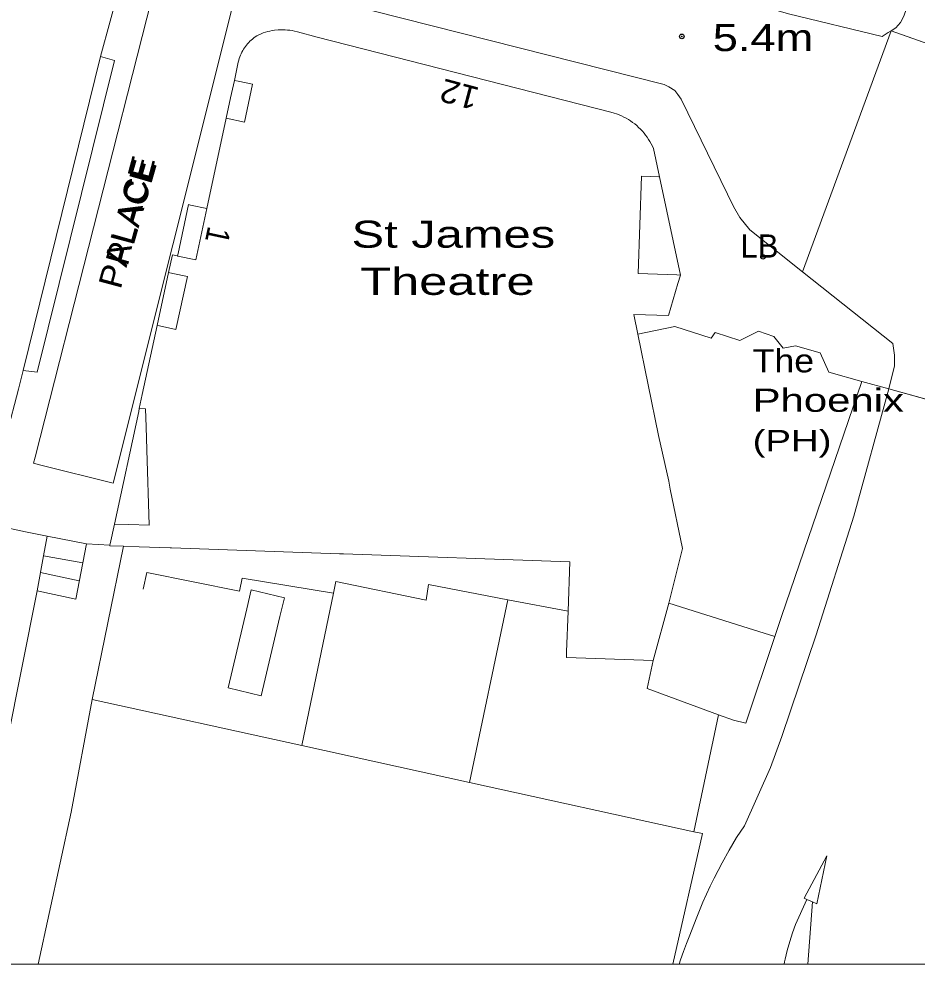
# Model space of a CAD drawing. Extents: x 528790 to 529292, y 179350 to 179856.
# Drawn here: x 529015 to 529073.1, y 179356 to 179417.1 of the extents above; entities that cross this region are included whole.
import ezdxf

# ---------------------------------------------------------------- set-up
doc = ezdxf.new("R2010")
doc.units = 0
doc.header["$LTSCALE"] = 0.6
doc.header["$PDMODE"] = 32
doc.header["$PDSIZE"] = 0.3
for name, color, linetype, lineweight in [('1', 7, 'Continuous', 13), ('2', 7, 'Continuous', 13), ('7', 7, 'Continuous', 13)]:
    doc.layers.add(name, color=color, linetype=linetype, lineweight=lineweight)
doc.layers.add('3', color=7, linetype='Continuous')
doc.layers.add('5', color=7, linetype='Continuous')

msp = doc.modelspace()

# ---------------------------------------------------------------- linework, layer by layer
at = {"layer": '1'}
for points in [[(529098.25, 179465.2), (529099.6, 179467.2), (529101.25, 179469.3), (529102.95, 179471.55), (529104.35, 179473.5), (529107.6, 179479.8), (529101.31, 179483.07), (529100.25, 179481.25), (529098.95, 179478.8), (529097.6, 179476.3), (529096.35, 179473.9), (529094.8, 179471.55), (529094, 179470.3), (529093, 179469.05), (529089.8, 179465.7), (529088.7, 179464.65), (529072.2, 179417.3), (529072, 179416.9), (529071.7, 179416.55), (529071.39, 179416.36), (529080.46, 179413.16)], [(529065.66, 179400.79), (529071.39, 179416.36), (529071.2, 179416.25), (529070.8, 179416), (529064.75, 179417.45), (529051.75, 179421.2), (529039.55, 179424.7), (529033.24, 179426.5), (529031.249, 179419.354), (529032.25, 179419.1), (529056.7, 179412.9), (529057, 179412.75), (529057.4, 179412.5), (529057.6, 179412.25), (529057.8, 179411.95), (529060.8, 179405.8), (529061.2, 179405), (529061.6, 179404.3), (529062.25, 179403.5)], [(529015.25, 179394.4), (529016.15, 179394.3), (529021.15, 179414.45), (529020.25, 179414.7)], [(529028.383, 179410.711), (529029.556, 179410.459), (529030.082, 179412.903), (529029.154, 179413.103), (529028.91, 179413.155), (529028.667, 179412.029)], [(529057.76, 179400.572), (529056.403, 179406.926), (529056.354, 179406.918), (529055.237, 179406.972), (529055.024, 179400.665), (529057.535, 179400.588)], [(529027.125, 179404.874), (529026.079, 179405.1), (529025.952, 179405.127), (529025.273, 179401.973), (529025.237, 179401.804), (529025.249, 179401.801), (529026.409, 179401.55)], [(529023.922, 179397.321), (529024.064, 179397.291), (529025.135, 179397.06), (529025.872, 179400.481), (529024.939, 179400.682), (529024.66, 179400.742)], [(529069.5, 179393.7), (529067.35, 179394.3), (529066.8, 179395.55), (529065.2, 179396), (529064.4, 179395.85), (529063.8, 179396.6), (529062.8, 179396.95), (529061.6, 179396.35), (529060, 179396.85), (529059.75, 179396.5), (529057.4, 179397.25), (529055, 179396.75), (529056.35, 179390.2), (529057, 179387.25), (529057.106, 179386.738), (529057.9, 179382.9), (529057, 179379.35), (529061.8, 179377.85), (529063.87, 179377.2), (529064.3, 179378.5)], [(529057.67, 179356.024), (529057.76, 179356.29), (529057.96, 179356.83), (529058.16, 179357.36), (529058.36, 179357.9), (529058.78, 179358.96), (529059.22, 179360.02), (529059.45, 179360.54), (529059.69, 179361.06), (529059.94, 179361.57), (529060.2, 179362.08), (529060.47, 179362.58), (529060.91, 179363.4), (529061.38, 179364.2), (529061.9, 179364.96), (529063.58, 179368.74), (529064.31, 179370.74), (529066.55, 179377.31), (529068.97, 179384.99), (529071.23, 179393.21), (529069.5, 179393.7), (529064.3, 179378.5), (529063.87, 179377.2), (529062, 179371.6), (529061.2, 179371.8), (529060.23, 179372.15), (529058.63, 179364.58), (529059.18, 179364.46), (529057.271, 179356.024)], [(529023.246, 179389.27), (529023.202, 179390.756), (529023.168, 179391.917), (529022.763, 179391.935), (529022.723, 179391.752), (529021.155, 179384.475), (529022.085, 179384.445), (529023.39, 179384.402)], [(529019.11, 179381.96), (529019.35, 179383.2), (529016.8, 179383.7), (529016.56, 179382.41)], [(529050.6, 179382.032), (529035.962, 179382.541), (529035.7, 179382.55), (529034.494, 179382.592), (529024.835, 179382.928), (529024.748, 179382.931), (529022.75, 179383), (529021.747, 179383.035), (529019.71, 179373.14), (529033.271, 179370.158), (529035.321, 179380), (529035.472, 179380.769), (529041.317, 179379.562), (529041.467, 179380.561), (529046.601, 179379.583), (529050.49, 179378.842)], [(529019.11, 179381.96), (529016.56, 179382.41), (529016.15, 179380.15), (529018.65, 179379.61)], [(529028.514, 179373.877), (529029.719, 179378.994), (529030.006, 179380.214), (529032.143, 179379.711), (529031.856, 179378.491), (529030.651, 179373.374)], [(529031.856, 179378.491), (529032.143, 179379.711), (529030.006, 179380.214), (529029.719, 179378.994), (529028.514, 179373.877), (529030.651, 179373.374)], [(529035.472, 179380.769), (529035.321, 179380), (529033.271, 179370.158), (529044.115, 179367.773), (529046.601, 179379.583), (529041.467, 179380.561), (529041.317, 179379.562)], [(529060.23, 179372.15), (529055.6, 179373.85), (529056, 179375.65), (529050.387, 179375.845), (529050.4, 179376.21), (529050.49, 179378.842), (529046.601, 179379.583), (529044.115, 179367.773), (529058.63, 179364.58)], [(529060.23, 179372.15), (529061.2, 179371.8), (529062, 179371.6), (529063.87, 179377.2), (529061.8, 179377.85), (529057, 179379.35), (529056, 179375.65), (529055.6, 179373.85)], [(529016.212, 179356.024), (529057.271, 179356.024), (529059.18, 179364.46), (529058.63, 179364.58), (529044.115, 179367.773), (529033.271, 179370.158), (529019.71, 179373.14), (529018.36, 179365.84)], [(529066.3, 179360.05), (529066.58, 179359.92), (529067.23, 179363.03), (529065.76, 179360.29), (529065.94, 179360.21)], [(529064.471, 179356.024), (529066.003, 179356.024), (529066.3, 179360.05), (529065.94, 179360.21), (529065.2, 179358.59), (529065.01, 179358.04), (529064.83, 179357.48), (529064.67, 179356.91), (529064.54, 179356.34), (529064.5, 179356.17)]]:
    msp.add_lwpolyline(points, close=True, dxfattribs=at)
for points in [[(529011.35, 179432.8), (529024.8, 179428.9), (529025.83, 179428.61), (529033.24, 179426.5), (529039.55, 179424.7), (529051.75, 179421.2), (529064.75, 179417.45), (529070.8, 179416), (529071.2, 179416.25), (529071.39, 179416.36), (529071.7, 179416.55), (529072, 179416.9), (529072.2, 179417.3), (529088.7, 179464.65)], [(529012.9, 179421.75), (529015.15, 179421.15), (529015.4, 179422.1), (529021.6, 179420.55), (529021, 179419.55), (529021.5, 179419.3), (529020.25, 179414.7), (529021.15, 179414.45), (529016.15, 179394.3), (529015.25, 179394.4), (529014.95, 179393.2)], [(529014.95, 179393.2), (529015.25, 179394.4), (529020.25, 179414.7), (529021.5, 179419.3), (529021, 179419.55), (529015.15, 179421.15), (529012.9, 179421.75)], [(529054.098, 179410.789), (529054.246, 179410.711), (529054.391, 179410.627), (529054.532, 179410.537), (529054.67, 179410.442), (529054.803, 179410.341), (529054.932, 179410.234), (529055.057, 179410.122), (529055.185, 179409.997), (529055.299, 179409.874), (529055.408, 179409.747), (529055.512, 179409.616), (529055.611, 179409.48), (529055.703, 179409.341), (529055.79, 179409.197), (529055.871, 179409.051), (529055.946, 179408.901), (529056.014, 179408.748), (529056.403, 179406.926), (529057.76, 179400.572), (529057.6, 179400.028), (529056.991, 179397.952), (529054.757, 179398.027), (529055, 179396.75), (529057.4, 179397.25), (529059.75, 179396.5), (529060, 179396.85), (529061.6, 179396.35), (529062.8, 179396.95), (529063.8, 179396.6), (529064.4, 179395.85), (529065.2, 179396), (529066.8, 179395.55), (529067.35, 179394.3), (529069.5, 179393.7), (529071.23, 179393.21), (529071.6, 179394.7), (529071.6, 179395.4), (529071.5, 179396.15), (529065.66, 179400.79), (529062.25, 179403.5), (529061.6, 179404.3), (529061.2, 179405), (529060.8, 179405.8), (529057.8, 179411.95), (529057.6, 179412.25), (529057.4, 179412.5), (529057, 179412.75), (529056.7, 179412.9), (529032.25, 179419.1)], [(529028.787, 179417.935), (529021.072, 179387.118), (529016.396, 179388.289), (529015.93, 179388.406), (529016.032, 179388.805), (529023.574, 179418.464)], [(529023.574, 179418.464), (529016.032, 179388.805), (529015.93, 179388.406), (529016.396, 179388.289), (529021.072, 179387.118), (529028.787, 179417.935)], [(529013.6, 179384.35), (529015.41, 179383.98), (529016.8, 179383.7), (529019.35, 179383.2), (529020.86, 179383.106), (529020.878, 179383.189), (529021.155, 179384.475), (529022.723, 179391.752), (529022.763, 179391.935), (529022.957, 179392.839), (529023.922, 179397.321), (529024.66, 179400.742), (529024.904, 179401.876), (529025.237, 179401.804), (529025.273, 179401.973), (529025.952, 179405.127), (529026.079, 179405.1), (529027.125, 179404.874), (529028.383, 179410.711), (529028.667, 179412.029), (529028.91, 179413.155), (529029.164, 179414.334), (529029.197, 179414.471), (529029.228, 179414.577), (529029.263, 179414.681), (529029.303, 179414.783), (529029.348, 179414.884), (529029.396, 179414.983), (529029.448, 179415.08), (529029.505, 179415.175), (529029.565, 179415.267), (529029.629, 179415.357), (529029.696, 179415.444), (529029.768, 179415.528), (529029.842, 179415.609), (529029.92, 179415.687), (529030, 179415.762), (529030.084, 179415.833), (529030.171, 179415.901), (529030.261, 179415.965), (529030.368, 179416.034), (529030.5, 179416.108), (529030.636, 179416.173), (529030.776, 179416.228), (529030.919, 179416.276), (529031.065, 179416.316), (529031.213, 179416.349), (529031.363, 179416.376), (529031.513, 179416.397), (529031.741, 179416.42), (529031.893, 179416.428), (529032.044, 179416.43), (529032.195, 179416.426), (529032.347, 179416.415), (529032.497, 179416.399), (529032.647, 179416.376), (529032.795, 179416.347), (529032.992, 179416.298), (529034.271, 179415.944), (529053.259, 179411.098), (529053.477, 179411.038), (529053.636, 179410.985), (529053.792, 179410.926), (529053.947, 179410.861), (529054.098, 179410.789)], [(529054.532, 179410.537), (529054.391, 179410.627), (529054.246, 179410.711), (529054.098, 179410.789), (529053.947, 179410.861), (529053.792, 179410.926), (529053.636, 179410.985), (529053.477, 179411.038), (529053.259, 179411.098), (529034.271, 179415.944), (529032.992, 179416.298), (529032.795, 179416.347), (529032.647, 179416.376), (529032.497, 179416.399), (529032.347, 179416.415), (529032.195, 179416.426), (529032.044, 179416.43), (529031.893, 179416.428), (529031.741, 179416.42), (529031.513, 179416.397), (529031.363, 179416.376), (529031.213, 179416.349), (529031.065, 179416.316), (529030.919, 179416.276), (529030.776, 179416.228), (529030.636, 179416.173), (529030.5, 179416.108), (529030.368, 179416.034), (529030.261, 179415.965), (529030.171, 179415.901), (529030.084, 179415.833), (529030, 179415.762), (529029.92, 179415.687), (529029.842, 179415.609), (529029.768, 179415.528), (529029.696, 179415.444), (529029.629, 179415.357), (529029.565, 179415.267), (529029.505, 179415.175), (529029.448, 179415.08), (529029.396, 179414.983), (529029.348, 179414.884), (529029.303, 179414.783), (529029.263, 179414.681), (529029.228, 179414.577), (529029.197, 179414.471), (529029.164, 179414.334), (529028.91, 179413.155), (529029.154, 179413.103), (529030.082, 179412.903), (529029.556, 179410.459), (529028.383, 179410.711), (529027.125, 179404.874), (529026.409, 179401.55), (529025.249, 179401.801), (529025.237, 179401.804), (529024.904, 179401.876), (529024.66, 179400.742), (529024.939, 179400.682), (529025.872, 179400.481), (529025.135, 179397.06), (529024.064, 179397.291), (529023.922, 179397.321), (529022.957, 179392.839), (529022.763, 179391.935), (529023.168, 179391.917), (529023.202, 179390.756), (529023.246, 179389.27), (529023.39, 179384.402), (529022.085, 179384.445), (529021.155, 179384.475), (529020.878, 179383.189), (529020.86, 179383.106), (529020.852, 179383.066), (529021.747, 179383.035), (529022.75, 179383), (529024.748, 179382.931), (529024.835, 179382.928), (529034.494, 179382.592), (529035.7, 179382.55), (529035.962, 179382.541), (529050.6, 179382.032), (529050.49, 179378.842), (529050.4, 179376.21), (529050.387, 179375.845), (529056, 179375.65), (529057, 179379.35), (529057.9, 179382.9), (529057.106, 179386.738), (529057, 179387.25), (529056.35, 179390.2), (529055, 179396.75), (529054.757, 179398.027), (529056.991, 179397.952), (529057.6, 179400.028), (529057.76, 179400.572), (529057.535, 179400.588), (529055.024, 179400.665), (529055.237, 179406.972), (529056.354, 179406.918), (529056.403, 179406.926)], [(529080.46, 179413.16), (529071.39, 179416.36), (529065.66, 179400.79), (529071.5, 179396.15), (529071.6, 179395.4), (529071.6, 179394.7), (529071.23, 179393.21), (529078.34, 179391.23)], [(529056.403, 179406.926), (529056.014, 179408.748), (529055.946, 179408.901), (529055.871, 179409.051), (529055.79, 179409.197), (529055.703, 179409.341), (529055.611, 179409.48), (529055.512, 179409.616), (529055.408, 179409.747), (529055.299, 179409.874), (529055.185, 179409.997), (529055.057, 179410.122), (529054.932, 179410.234), (529054.803, 179410.341), (529054.67, 179410.442), (529054.532, 179410.537)], [(529078.34, 179391.23), (529071.23, 179393.21), (529068.97, 179384.99), (529066.55, 179377.31), (529064.31, 179370.74), (529063.58, 179368.74), (529061.9, 179364.96), (529061.38, 179364.2), (529060.91, 179363.4), (529060.47, 179362.58), (529060.2, 179362.08), (529059.94, 179361.57), (529059.69, 179361.06), (529059.45, 179360.54), (529059.22, 179360.02), (529058.78, 179358.96), (529058.36, 179357.9), (529058.16, 179357.36), (529057.96, 179356.83), (529057.76, 179356.29), (529057.67, 179356.024), (529064.471, 179356.024), (529064.5, 179356.17), (529064.54, 179356.34), (529064.67, 179356.91), (529064.83, 179357.48), (529065.01, 179358.04), (529065.2, 179358.59), (529065.94, 179360.21), (529065.76, 179360.29), (529067.23, 179363.03), (529066.58, 179359.92), (529066.3, 179360.05), (529066.003, 179356.024), (529079.274, 179356.024)], [(529012.23, 179360.57), (529016.15, 179380.15), (529016.56, 179382.41), (529016.8, 179383.7), (529015.41, 179383.98), (529013.6, 179384.35)], [(529009.327, 179356.024), (529016.212, 179356.024), (529018.36, 179365.84), (529019.71, 179373.14), (529021.747, 179383.035), (529020.852, 179383.066), (529020.86, 179383.106), (529019.35, 179383.2), (529019.11, 179381.96), (529018.65, 179379.61), (529016.15, 179380.15), (529012.23, 179360.57)]]:
    msp.add_lwpolyline(points, dxfattribs=at)
at = {"layer": '2'}
for p, q in [((529071.39, 179416.36), (529065.66, 179400.79)), ((529071.39, 179416.36), (529080.46, 179413.16)), ((529020.25, 179414.7), (529015.25, 179394.4)), ((529027.125, 179404.874), (529028.383, 179410.711)), ((529056.403, 179406.926), (529057.76, 179400.572)), ((529023.922, 179397.321), (529024.66, 179400.742)), ((529071.23, 179393.21), (529069.5, 179393.7)), ((529078.34, 179391.23), (529071.23, 179393.21)), ((529016.8, 179383.7), (529016.56, 179382.41)), ((529019.35, 179383.2), (529016.8, 179383.7)), ((529019.35, 179383.2), (529019.11, 179381.96)), ((529020.86, 179383.106), (529019.35, 179383.2)), ((529021.747, 179383.035), (529019.71, 179373.14)), ((529016.56, 179382.41), (529016.15, 179380.15)), ((529019.11, 179381.96), (529016.56, 179382.41)), ((529019.11, 179381.96), (529018.65, 179379.61)), ((529018.88, 179380.8), (529016.37, 179381.35)), ((529016.15, 179380.15), (529018.65, 179379.61)), ((529035.321, 179380), (529033.271, 179370.158)), ((529046.601, 179379.583), (529044.115, 179367.773)), ((529046.601, 179379.583), (529050.49, 179378.842)), ((529056, 179375.65), (529057, 179379.35)), ((529019.71, 179373.14), (529033.271, 179370.158)), ((529060.23, 179372.15), (529058.63, 179364.58)), ((529033.271, 179370.158), (529044.115, 179367.773)), ((529044.115, 179367.773), (529058.63, 179364.58)), ((529065.94, 179360.21), (529066.3, 179360.05)), ((529066.3, 179360.05), (529066.003, 179356.024))]:
    msp.add_line(p, q, dxfattribs=at)
for points in [[(529071.39, 179416.36), (529071.7, 179416.55), (529072, 179416.9), (529072.2, 179417.3), (529088.7, 179464.65), (529089.8, 179465.7), (529093, 179469.05), (529094, 179470.3), (529094.8, 179471.55), (529096.35, 179473.9), (529097.6, 179476.3), (529098.95, 179478.8), (529100.25, 179481.25), (529101.31, 179483.07)], [(529071.39, 179416.36), (529071.2, 179416.25), (529070.8, 179416), (529064.75, 179417.45), (529051.75, 179421.2), (529039.55, 179424.7), (529033.24, 179426.5)], [(529020.25, 179414.7), (529021.5, 179419.3), (529021, 179419.55)], [(529065.66, 179400.79), (529062.25, 179403.5), (529061.6, 179404.3), (529061.2, 179405), (529060.8, 179405.8), (529057.8, 179411.95), (529057.6, 179412.25), (529057.4, 179412.5), (529057, 179412.75), (529056.7, 179412.9), (529032.25, 179419.1), (529031.249, 179419.354)], [(529023.574, 179418.464), (529016.032, 179388.805), (529015.93, 179388.406), (529016.396, 179388.289), (529021.072, 179387.118), (529028.787, 179417.935)], [(529028.91, 179413.155), (529029.164, 179414.334), (529029.197, 179414.471), (529029.228, 179414.577), (529029.263, 179414.681), (529029.303, 179414.783), (529029.348, 179414.884), (529029.396, 179414.983), (529029.448, 179415.08), (529029.505, 179415.175), (529029.565, 179415.267), (529029.629, 179415.357), (529029.696, 179415.444), (529029.768, 179415.528), (529029.842, 179415.609), (529029.92, 179415.687), (529030, 179415.762), (529030.084, 179415.833), (529030.171, 179415.901), (529030.261, 179415.965), (529030.368, 179416.034), (529030.5, 179416.108), (529030.636, 179416.173), (529030.776, 179416.228), (529030.919, 179416.276), (529031.065, 179416.316), (529031.213, 179416.349), (529031.363, 179416.376), (529031.513, 179416.397), (529031.741, 179416.42), (529031.893, 179416.428), (529032.044, 179416.43), (529032.195, 179416.426), (529032.347, 179416.415), (529032.497, 179416.399), (529032.647, 179416.376), (529032.795, 179416.347), (529032.992, 179416.298), (529034.271, 179415.944), (529053.259, 179411.098), (529053.477, 179411.038), (529053.636, 179410.985), (529053.792, 179410.926), (529053.947, 179410.861), (529054.098, 179410.789), (529054.246, 179410.711), (529054.391, 179410.627), (529054.532, 179410.537), (529054.67, 179410.442), (529054.803, 179410.341), (529054.932, 179410.234), (529055.057, 179410.122), (529055.185, 179409.997), (529055.299, 179409.874), (529055.408, 179409.747), (529055.512, 179409.616), (529055.611, 179409.48), (529055.703, 179409.341), (529055.79, 179409.197), (529055.871, 179409.051), (529055.946, 179408.901), (529056.014, 179408.748), (529056.403, 179406.926)], [(529015.25, 179394.4), (529016.15, 179394.3), (529021.15, 179414.45), (529020.25, 179414.7)], [(529028.383, 179410.711), (529028.667, 179412.029), (529028.91, 179413.155)], [(529028.91, 179413.155), (529029.154, 179413.103), (529030.082, 179412.903), (529029.556, 179410.459), (529028.383, 179410.711)], [(529057.76, 179400.572), (529057.535, 179400.588), (529055.024, 179400.665), (529055.237, 179406.972), (529056.354, 179406.918), (529056.403, 179406.926)], [(529027.125, 179404.874), (529026.079, 179405.1), (529025.952, 179405.127), (529025.273, 179401.973), (529025.237, 179401.804)], [(529025.237, 179401.804), (529025.249, 179401.801), (529026.409, 179401.55), (529027.125, 179404.874)], [(529025.237, 179401.804), (529024.904, 179401.876), (529024.66, 179400.742)], [(529024.66, 179400.742), (529024.939, 179400.682), (529025.872, 179400.481), (529025.135, 179397.06), (529024.064, 179397.291), (529023.922, 179397.321)], [(529057.76, 179400.572), (529057.6, 179400.028), (529056.991, 179397.952), (529054.757, 179398.027), (529055, 179396.75)], [(529071.23, 179393.21), (529071.6, 179394.7), (529071.6, 179395.4), (529071.5, 179396.15), (529065.66, 179400.79)], [(529022.763, 179391.935), (529022.957, 179392.839), (529023.922, 179397.321)], [(529069.5, 179393.7), (529067.35, 179394.3), (529066.8, 179395.55), (529065.2, 179396), (529064.4, 179395.85), (529063.8, 179396.6), (529062.8, 179396.95), (529061.6, 179396.35), (529060, 179396.85), (529059.75, 179396.5), (529057.4, 179397.25), (529055, 179396.75)], [(529057, 179379.35), (529057.9, 179382.9), (529057.106, 179386.738), (529057, 179387.25), (529056.35, 179390.2), (529055, 179396.75)], [(529015.25, 179394.4), (529014.95, 179393.2), (529014.2, 179390.3), (529013.95, 179389.35)], [(529063.87, 179377.2), (529064.3, 179378.5), (529069.5, 179393.7)], [(529057.67, 179356.024), (529057.76, 179356.29), (529057.96, 179356.83), (529058.16, 179357.36), (529058.36, 179357.9), (529058.78, 179358.96), (529059.22, 179360.02), (529059.45, 179360.54), (529059.69, 179361.06), (529059.94, 179361.57), (529060.2, 179362.08), (529060.47, 179362.58), (529060.91, 179363.4), (529061.38, 179364.2), (529061.9, 179364.96), (529063.58, 179368.74), (529064.31, 179370.74), (529066.55, 179377.31), (529068.97, 179384.99), (529071.23, 179393.21)], [(529021.155, 179384.475), (529022.085, 179384.445), (529023.39, 179384.402), (529023.246, 179389.27), (529023.202, 179390.756), (529023.168, 179391.917), (529022.763, 179391.935)], [(529021.155, 179384.475), (529022.723, 179391.752), (529022.763, 179391.935)], [(529020.86, 179383.106), (529020.878, 179383.189), (529021.155, 179384.475)], [(529016.8, 179383.7), (529015.41, 179383.98), (529013.6, 179384.35)], [(529021.747, 179383.035), (529020.852, 179383.066), (529020.86, 179383.106)], [(529050.49, 179378.842), (529050.6, 179382.032), (529035.962, 179382.541), (529035.7, 179382.55), (529034.494, 179382.592), (529024.835, 179382.928), (529024.748, 179382.931), (529022.75, 179383), (529021.747, 179383.035)], [(529023.023, 179380.261), (529023.249, 179381.338), (529029.249, 179380.131), (529029.419, 179380.975), (529035.321, 179380)], [(529035.321, 179380), (529035.472, 179380.769), (529041.317, 179379.562), (529041.467, 179380.561), (529046.601, 179379.583)], [(529016.15, 179380.15), (529012.23, 179360.57), (529012.19, 179360.39), (529012.14, 179360.21), (529012.08, 179360.03), (529011.94, 179359.67), (529011.86, 179359.5), (529011.77, 179359.33), (529011.68, 179359.17), (529011.58, 179359.01), (529011.47, 179358.86), (529011.35, 179358.72), (529011.09, 179358.46), (529010.81, 179358.2), (529010.55, 179357.94), (529010.42, 179357.8), (529010.24, 179357.57), (529010.06, 179357.33), (529009.9, 179357.08), (529009.6, 179356.56), (529009.46, 179356.3), (529009.33, 179356.03), (529009.327, 179356.024)], [(529057, 179379.35), (529061.8, 179377.85), (529063.87, 179377.2)], [(529056, 179375.65), (529050.387, 179375.845), (529050.4, 179376.21), (529050.49, 179378.842)], [(529060.23, 179372.15), (529061.2, 179371.8), (529062, 179371.6), (529063.87, 179377.2)], [(529060.23, 179372.15), (529055.6, 179373.85), (529056, 179375.65)], [(529016.212, 179356.024), (529018.36, 179365.84), (529019.71, 179373.14)], [(529058.63, 179364.58), (529059.18, 179364.46), (529057.271, 179356.024)], [(529066.3, 179360.05), (529066.58, 179359.92), (529067.23, 179363.03), (529065.76, 179360.29), (529065.94, 179360.21)], [(529064.471, 179356.024), (529064.5, 179356.17), (529064.54, 179356.34), (529064.67, 179356.91), (529064.83, 179357.48), (529065.01, 179358.04), (529065.2, 179358.59), (529065.94, 179360.21)]]:
    msp.add_lwpolyline(points, dxfattribs=at)
msp.add_lwpolyline([(529031.856, 179378.491), (529032.143, 179379.711), (529030.006, 179380.214), (529029.719, 179378.994), (529028.514, 179373.877), (529030.651, 179373.374)], close=True, dxfattribs=at)
at = {"layer": '3'}
for p in [(529057.85, 179416), (529063.1, 179401.75)]:
    msp.add_point(p, dxfattribs=at)
at = {"layer": '7'}
msp.add_lwpolyline([(528790.22, 179356.024), (529290.22, 179356.024), (529290.22, 179856.024), (528790.22, 179856.024)], close=True, dxfattribs=at)

# ---------------------------------------------------------------- texts
at = {"layer": '5'}
for s, height, width, p in [('5.4m', 1.75, 1.25, (529059.85, 179415.05)), ('St James', 1.75, 1.35, (529036.49, 179402.34)), ('Theatre', 1.75, 1.4, (529037.04, 179399.29)), ('The', 1.5, 1.15, (529062.43, 179394.28)), ('Phoenix', 1.5, 1.35, (529062.43, 179391.73)), ('(PH)', 1.375, 1.35, (529062.43, 179389.18))]:
    msp.add_text(s, height=height, dxfattribs=dict(at, width=width)).set_placement(p)
for s, rotation, width, p in [('12', 165, 1.1, (529044.84, 179412.66)), ('PALACE', 75, 1.1, (529021.55, 179399.6)), ('PLACE', 74, 1.05, (529022, 179401.1)), ('1', 258, 0.9, (529027.22, 179403.79))]:
    msp.add_text(s, height=1.5, rotation=rotation, dxfattribs=dict(at, width=width)).set_placement(p)
msp.add_text('LB', height=1.5, dxfattribs=at).set_placement((529061.65, 179401.7))

doc.saveas('drawing.dxf')
